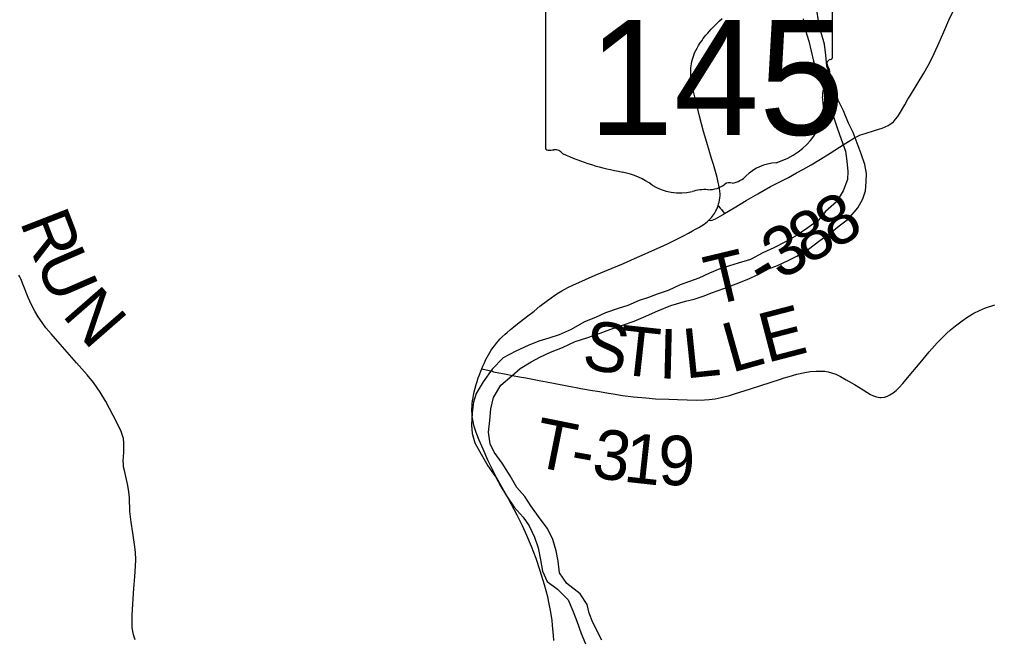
# Model space of a CAD drawing. Extents: x 0 to 34, y 0 to 22.
# Drawn here: x 4.132 to 5.245, y 15.221 to 15.933 of the extents above; entities that cross this region are included whole.
import ezdxf

# ---------------------------------------------------------------- set-up
doc = ezdxf.new("R2010")
doc.units = 0
for name, color, linetype in [('GM_X_Major_River', 7, 'Continuous'), ('GM_X_State_Location', 7, 'Continuous'), ('GM_X_State_Route', 7, 'Continuous'), ('GM_X_State_Shield', 7, 'Continuous'), ('GM_X_Township_Road', 7, 'Continuous'), ('GM_X_Township_Road_Text', 7, 'Continuous')]:
    doc.layers.add(name, color=color, linetype=linetype)

msp = doc.modelspace()

# ---------------------------------------------------------------- linework, layer by layer
at = {"layer": 'GM_X_Major_River'}
for points in [[(5.0311, 15.9335), (5.0335, 15.9202), (5.0375, 15.9081), (5.0403, 15.8964), (5.0427, 15.8851), (5.0474, 15.8719), (5.0529, 15.8579), (5.0573, 15.8451), (5.0616, 15.8318), (5.066, 15.8201), (5.0699, 15.8084), (5.0746, 15.7956), (5.0794, 15.7816), (5.081, 15.7703), (5.0823, 15.7585), (5.0817, 15.7491), (5.077, 15.7361), (5.0692, 15.7235), (5.0568, 15.7127), (5.0486, 15.7027), (5.0351, 15.693), (5.0242, 15.6853), (5.0106, 15.6779), (4.9975, 15.6709), (4.9847, 15.665), (4.9707, 15.6576), (4.9564, 15.6533), (4.9466, 15.6501), (4.9352, 15.6469), (4.9236, 15.6418), (4.9111, 15.636), (4.9006, 15.6324), (4.89, 15.6285), (4.8761, 15.6218), (4.8636, 15.6179), (4.8534, 15.6139), (4.8428, 15.6104), (4.8296, 15.6049), (4.8187, 15.6013), (4.804, 15.5962), (4.7927, 15.5911), (4.7802, 15.586), (4.7648, 15.5771), (4.7509, 15.5712), (4.7392, 15.5672), (4.7278, 15.5637), (4.7154, 15.559), (4.7011, 15.5523), (4.6868, 15.5445), (4.6741, 15.5315), (4.6636, 15.5173), (4.6559, 15.5039), (4.6526, 15.494), (4.6512, 15.4815), (4.6503, 15.4674), (4.6512, 15.4579), (4.654, 15.447), (4.6614, 15.4342), (4.6691, 15.4206), (4.6784, 15.4078), (4.6842, 15.3969), (4.6904, 15.3864), (4.6993, 15.3732), (4.7097, 15.362), (4.7167, 15.3518)], [(4.7186, 15.375), (4.7117, 15.3855), (4.7024, 15.396), (4.6947, 15.4092), (4.6854, 15.4239), (4.6765, 15.4363), (4.6718, 15.4461), (4.6697, 15.4593), (4.6714, 15.4726), (4.6724, 15.4863), (4.6756, 15.4992), (4.6842, 15.5134), (4.6965, 15.5242), (4.7063, 15.5323), (4.7187, 15.54), (4.7288, 15.5455), (4.7409, 15.5513), (4.7549, 15.5565), (4.7695, 15.5635), (4.7828, 15.5675), (4.7979, 15.573), (4.8092, 15.5773), (4.8235, 15.5821), (4.8371, 15.5868), (4.8476, 15.5915), (4.8642, 15.5985), (4.8793, 15.6048), (4.8959, 15.6096), (4.9058, 15.612), (4.9163, 15.6156), (4.9269, 15.6195), (4.9401, 15.6242), (4.954, 15.6297), (4.9669, 15.6344), (4.9801, 15.6407), (4.9913, 15.6469), (5.0015, 15.6505), (5.0136, 15.6563), (5.0238, 15.6614), (5.0373, 15.6695), (5.0501, 15.6792), (5.0621, 15.6877), (5.0722, 15.6962), (5.0831, 15.7043), (5.0939, 15.7166), (5.0995, 15.7269), (5.1024, 15.7364), (5.1034, 15.7467), (5.1036, 15.7562), (5.1019, 15.7664), (5.0976, 15.7789), (5.0882, 15.803), (5.0831, 15.8139), (5.0772, 15.8279), (5.071, 15.8403), (5.0674, 15.8535), (5.0631, 15.8656), (5.0583, 15.8792), (5.057, 15.8921), (5.0553, 15.9046), (5.0514, 15.919), (5.0485, 15.9314), (5.0468, 15.9435)], [(4.8, 15.2206), (4.7898, 15.2409), (4.7855, 15.2518), (4.7831, 15.2617), (4.775, 15.2741), (4.7597, 15.2856), (4.7515, 15.2981), (4.7498, 15.3113), (4.7474, 15.3234), (4.7438, 15.3363), (4.7376, 15.3487), (4.7291, 15.36), (4.7186, 15.375)], [(4.7167, 15.3518), (4.7225, 15.339), (4.7269, 15.3266), (4.7297, 15.3129), (4.7318, 15.3001), (4.7373, 15.288), (4.7491, 15.2791), (4.7614, 15.2671), (4.7665, 15.2546), (4.7712, 15.2425), (4.7763, 15.2286), (4.7811, 15.2165)]]:
    msp.add_lwpolyline(points, dxfattribs=at)
at = {"layer": 'GM_X_State_Route'}
msp.add_lwpolyline([(4.7447, 15.2205), (4.7444, 15.2266), (4.7435, 15.2376), (4.7428, 15.2438), (4.7411, 15.2547), (4.7396, 15.2626), (4.7378, 15.2705), (4.7341, 15.2842), (4.7292, 15.3002), (4.7244, 15.3143), (4.7192, 15.3283), (4.714, 15.3409), (4.7089, 15.3521), (4.7027, 15.3643), (4.6927, 15.3829), (4.6795, 15.4068), (4.673, 15.4195), (4.6692, 15.4274), (4.6638, 15.4399), (4.6593, 15.4502), (4.6559, 15.4589), (4.6547, 15.4625), (4.6536, 15.466), (4.6528, 15.4693), (4.6521, 15.4721), (4.6516, 15.4752), (4.6513, 15.4777), (4.651, 15.4807), (4.6509, 15.4833), (4.6508, 15.4861), (4.651, 15.489), (4.6512, 15.4919), (4.6516, 15.4952), (4.6521, 15.4988), (4.6527, 15.502), (4.6535, 15.5057), (4.6545, 15.5099), (4.6556, 15.514), (4.6568, 15.5177), (4.6582, 15.5219), (4.6595, 15.5253), (4.6614, 15.5304), (4.6621, 15.532), (4.6634, 15.5352), (4.6651, 15.5391), (4.6668, 15.5426), (4.6683, 15.5456), (4.6697, 15.5481), (4.6714, 15.5509), (4.673, 15.5534), (4.6748, 15.5561), (4.6766, 15.5585), (4.679, 15.5615), (4.681, 15.5638), (4.6834, 15.5665), (4.6857, 15.5688), (4.689, 15.572), (4.6912, 15.5739), (4.695, 15.5773), (4.6988, 15.5803), (4.703, 15.5836), (4.7067, 15.5864), (4.7151, 15.5928), (4.7222, 15.5983), (4.7289, 15.6038), (4.7376, 15.6105), (4.7419, 15.6136), (4.7459, 15.6164), (4.7502, 15.6191), (4.7539, 15.6214), (4.7575, 15.6235), (4.7616, 15.6256), (4.7666, 15.628), (4.7813, 15.6346), (4.7922, 15.6394), (4.8249, 15.653), (4.8374, 15.6585), (4.8436, 15.6613), (4.8702, 15.6733), (4.8759, 15.6759), (4.882, 15.6789), (4.8882, 15.6819), (4.8936, 15.6847), (4.8993, 15.6877), (4.9041, 15.6902), (4.9076, 15.6921), (4.9111, 15.6941), (4.9142, 15.696), (4.9172, 15.6982), (4.9192, 15.6997), (4.9211, 15.7012), (4.9228, 15.7027), (4.9242, 15.7041), (4.9257, 15.7057), (4.9271, 15.7073), (4.9281, 15.7087), (4.9292, 15.7102), (4.9301, 15.7117), (4.9309, 15.7134), (4.9319, 15.7152), (4.9327, 15.7173), (4.9334, 15.7192), (4.934, 15.7213), (4.9345, 15.7233), (4.9349, 15.7255), (4.9354, 15.7281), (4.9356, 15.7306), (4.9356, 15.7327), (4.9354, 15.7357), (4.9351, 15.7388), (4.9343, 15.7429), (4.9336, 15.746), (4.9322, 15.7516), (4.931, 15.7556), (4.928, 15.7664), (4.9259, 15.7735), (4.9204, 15.7919), (4.9168, 15.8045), (4.9122, 15.8219), (4.9088, 15.8351), (4.9051, 15.8501), (4.9035, 15.8574), (4.9026, 15.8629), (4.9022, 15.8663), (4.9021, 15.8692), (4.902, 15.8721), (4.902, 15.8748), (4.9021, 15.8774), (4.9024, 15.8798), (4.9027, 15.8821), (4.9033, 15.8848), (4.9038, 15.8872), (4.9046, 15.8897), (4.9055, 15.8921), (4.9064, 15.8944), (4.9078, 15.8973), (4.9092, 15.9), (4.9109, 15.9029), (4.9128, 15.9059), (4.9146, 15.9085), (4.9164, 15.911), (4.9194, 15.9147), (4.9216, 15.9173), (4.9256, 15.9218), (4.9287, 15.9251), (4.9322, 15.9285), (4.9349, 15.9312), (4.938, 15.934)], dxfattribs=at)
at = {"layer": 'GM_X_State_Shield'}
for p, q in [((5.0648, 15.8903), (5.0648, 15.9949)), ((4.7352, 15.9865), (4.7352, 15.7864)), ((5.0647, 15.8903), (5.0648, 15.8903))]:
    msp.add_line(p, q, dxfattribs=at)
for centre, major_axis, start_param, end_param in [((5.0609, 15.8899), (0.00393, 0), 5.05454, 6.418171), ((5.0639, 15.8826), (0.00568, 0), 1.883978, 3.671073), ((5.0278, 15.8693), (0.0341, 0), 5.934695, 6.695948), ((5.0779, 15.8464), (0.0248, 0), 2.387724, 3.262537), ((4.9669, 15.8331), (0.0874, 0), 5.101752, 6.440018), ((4.739, 15.786), (0.00385, 0), 3.00124, 4.508301), ((4.7396, 15.8065), (0.0294, 0), 4.665946, 4.897461), ((4.7456, 15.7749), (0.0106, 0), 0.519207, 1.627899), ((4.8794, 15.9547), (0.2524, 0), 4.195997, 4.488961), ((5.0038, 15.7302), (0.0479, 0), 1.647645, 2.488434), ((4.8042, 15.6965), (0.079, 0), 0.823519, 1.323587), ((4.9222, 15.7589), (0.0267, 0), 4.691044, 5.507374), ((4.9463, 15.7395), (0.00752, 0), 1.147584, 2.315152), ((4.9431, 15.767), (0.0282, 0), 4.937069, 5.64225), ((4.8896, 15.7739), (0.0501, 0), 4.026481, 4.996735), ((4.9185, 15.7047), (0.0412, 0), 1.495662, 1.94098)]:
    msp.add_ellipse(centre, major_axis=major_axis, ratio=0.8, start_param=start_param, end_param=end_param, dxfattribs=at)
at = {"layer": 'GM_X_Township_Road'}
for points in [[(4.9406, 15.7103), (4.9517, 15.7169), (4.9655, 15.7252), (4.9789, 15.733), (4.9936, 15.7412), (5.0035, 15.7464), (5.014, 15.7516), (5.0232, 15.7568), (5.0312, 15.7611), (5.04, 15.7662), (5.0507, 15.7725), (5.0618, 15.7794), (5.078, 15.7897), (5.088, 15.796), (5.0903, 15.7974), (5.0929, 15.7987), (5.0969, 15.8004), (5.1022, 15.8022), (5.1141, 15.8057), (5.1218, 15.8081), (5.1252, 15.8095), (5.1285, 15.8112), (5.1321, 15.8136), (5.1345, 15.8156), (5.1371, 15.8183), (5.1397, 15.8217), (5.1428, 15.8264), (5.1477, 15.835), (5.1513, 15.8414), (5.152, 15.8425), (5.1542, 15.8462), (5.1693, 15.8711), (5.1745, 15.8802), (5.1791, 15.889), (5.1856, 15.9031), (5.1914, 15.9161), (5.1983, 15.9321), (5.2045, 15.9456)], [(4.9334, 15.7192), (4.9356, 15.7165), (4.9372, 15.7147), (4.939, 15.7123), (4.9406, 15.7103)], [(4.9228, 15.7027), (4.9248, 15.7024), (4.9266, 15.7026), (4.9303, 15.7043), (4.9383, 15.7089), (4.9406, 15.7103)], [(4.2643, 15.2211), (4.2628, 15.2258), (4.2618, 15.2307), (4.2611, 15.2356), (4.2608, 15.2418), (4.2609, 15.2499), (4.2629, 15.2802), (4.2641, 15.2938), (4.2649, 15.3056), (4.265, 15.313), (4.2646, 15.3217), (4.2637, 15.3304), (4.2616, 15.3439), (4.2596, 15.3561), (4.2589, 15.3623), (4.2584, 15.3685), (4.2577, 15.384), (4.2571, 15.3908), (4.256, 15.3981), (4.2529, 15.412), (4.252, 15.4153), (4.251, 15.4196), (4.2509, 15.4226), (4.2506, 15.4263), (4.2509, 15.4315), (4.2513, 15.436), (4.2515, 15.4423), (4.2515, 15.4472), (4.251, 15.4521), (4.25, 15.4557), (4.2483, 15.4603), (4.2445, 15.4681), (4.2391, 15.4786), (4.2306, 15.4945), (4.2243, 15.5052), (4.2209, 15.5104), (4.2165, 15.5163), (4.2094, 15.525), (4.1971, 15.539), (4.1783, 15.5605), (4.168, 15.5721), (4.162, 15.5792), (4.1575, 15.5852), (4.1531, 15.5919), (4.1492, 15.5983), (4.1455, 15.6054), (4.1417, 15.6139), (4.1366, 15.6266), (4.1331, 15.6352), (4.1321, 15.6375), (4.1309, 15.6396)], [(4.8979, 15.4964), (4.9083, 15.4962), (4.9176, 15.4966), (4.9232, 15.497), (4.93, 15.4978), (4.9367, 15.4991), (4.9463, 15.5016), (4.9522, 15.5033), (4.9706, 15.5091), (4.9824, 15.5128), (4.993, 15.5163), (5.006, 15.5207), (5.009, 15.5216), (5.0149, 15.5234), (5.0239, 15.5258), (5.033, 15.5279), (5.0391, 15.5289), (5.0459, 15.5295), (5.0515, 15.5295), (5.0558, 15.5292), (5.0595, 15.5286), (5.0637, 15.5275), (5.0683, 15.5258), (5.0739, 15.5231), (5.0804, 15.5195), (5.0836, 15.5177), (5.09, 15.514), (5.0999, 15.5078), (5.1084, 15.5027), (5.1117, 15.5011), (5.1152, 15.4998), (5.1188, 15.4993), (5.1206, 15.4992), (5.1243, 15.4997), (5.1278, 15.5008), (5.1306, 15.5022), (5.1342, 15.5046), (5.1376, 15.5073), (5.1412, 15.5108), (5.1454, 15.5153), (5.1526, 15.5239), (5.1653, 15.5391), (5.1757, 15.5514), (5.1847, 15.5617), (5.1912, 15.5684), (5.1956, 15.5727), (5.2002, 15.5768), (5.206, 15.5815), (5.2133, 15.5871), (5.2199, 15.5917), (5.2268, 15.5958), (5.2335, 15.5991), (5.2404, 15.6019), (5.251, 15.6055)], [(4.6621, 15.532), (4.674, 15.5292), (4.6757, 15.5288), (4.6903, 15.5259), (4.6976, 15.5245), (4.7055, 15.5229), (4.7129, 15.5216), (4.7281, 15.5188), (4.7366, 15.5172), (4.7446, 15.5157), (4.7621, 15.5122), (4.7706, 15.5106), (4.776, 15.5096), (4.7894, 15.5072), (4.7949, 15.5063), (4.8015, 15.5051), (4.8076, 15.5042), (4.813, 15.5033), (4.8238, 15.5016), (4.8361, 15.5), (4.8503, 15.4988), (4.8616, 15.4978), (4.8769, 15.4971), (4.8866, 15.4968), (4.8979, 15.4964)]]:
    msp.add_lwpolyline(points, dxfattribs=at)

# ---------------------------------------------------------------- texts
at = {"layer": 'GM_X_State_Location'}
for s in ['s', 'r']:
    msp.add_text(s, height=0.000189, dxfattribs=at).set_placement((4.8963, 15.8732))
msp.add_text('145', height=0.000189, rotation=0, dxfattribs=at).set_placement((4.8294, 15.8594))
at = {"layer": 'GM_X_State_Shield'}
msp.add_text('145', height=0.13184, dxfattribs=at).set_placement((4.7843, 15.8005))
at = {"layer": 'GM_X_Township_Road_Text'}
for s, rotation, p in [('8', 30.3099, (5.0665, 15.6683)), ('R', 291.2267, (4.1316, 15.7009)), ('8', 29.606, (5.0354, 15.6506)), ('3', 29.4731, (5.0048, 15.6333)), ('U', 293.5152, (4.1494, 15.6551)), ('T', 13.4739, (4.9262, 15.6042)), ('-', 31.269, (4.9853, 15.6214)), ('N', 311.0863, (4.1793, 15.5935)), ('E', 14.5913, (4.9893, 15.5387)), ('S', 350.0917, (4.7756, 15.5333)), ('T', 353.7066, (4.8172, 15.5262)), ('I', 358.6214, (4.8648, 15.5212)), ('L', 5.8729, (4.896, 15.5209)), ('L', 15.7141, (4.9487, 15.5273)), ('T', 348.685, (4.7188, 15.421)), ('3', 352.0843, (4.787, 15.4079)), ('1', 353.7955, (4.8236, 15.4028)), ('9', 359.4827, (4.8645, 15.3987)), ('-', 349.7172, (4.7616, 15.4125))]:
    msp.add_text(s, height=0.0568, rotation=rotation, dxfattribs=at).set_placement(p)

doc.saveas('drawing.dxf')
